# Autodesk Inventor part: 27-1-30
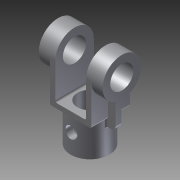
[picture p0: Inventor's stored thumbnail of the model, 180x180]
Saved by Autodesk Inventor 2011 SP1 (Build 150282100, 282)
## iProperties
Created: 2014-02
Part Number: 27-1-30
Document SubType Name: Modeling
Designer: Administrator
Density: 1 g/cm^3
Author: Administrator
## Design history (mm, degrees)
sketch "草图1"
  geometry: C1 r 20 at (0, 0); 1 further point
  constraints: 1 centre point, 1 coincident
  dimensions: "d0" = 40 diameter of C1
extrude "拉伸1" new body sketch "草图1" distance "d1" = 34; taper "d2" = 0 deg
node "工作平面1"
sketch "草图2"
  geometry: L1 (-20, 0)-(20, 0) reference; C1 r 6 at (0, 20); 1 further point
  constraints: 1 centre point
  dimensions: "d4" = 12 diameter of C1; "d5" = 20 distance of point (0, 0) C1.centre
extrude "拉伸2" cut sketch "草图2" stored distance "d6" = 34; taper "d7" = 0 deg
node "工作平面2"
sketch "草图3"
  geometry: L1 (-20, 34)-(20, 34) reference; C1 r 20 at (0, 76); 1 further point
  constraints: 1 centre point
  dimensions: "d9" = 40 diameter of C1; "d10" = 42 distance from line of L1 C1.centre
extrude "拉伸3" join sketch "草图3" distance "d11" = 17; taper "d12" = 0 deg
hole "Hole1" diameter "d15" = 24; stored, may be unused: countersink angle "d19" = 90 deg, drill point angle "d21" = 118 deg; dims "d13" = 10, "d14" = 10, "d16" = 6, "d17" = 4, "d18" = 2, "d20" = 8
sketch "草图4"
  geometry: L1 (-20, 34)-(20, 34) reference; L2 (20, 76)-(20, 34); L3 (-20, 76)-(-20, 34); A1 r 20 centre (0, 76) between (20, 76) and (-20, 76) reference; 1 further point
  constraints: 4 end point, 2 point on circle, 2 tangent, 1 parallel, 1 perpendicular
extrude "拉伸4" join sketch "草图4" distance "d22" = 5.5; taper "d23" = 0 deg
sketch "草图5"
  geometry: L1 (20, 34)-(20, 76) reference; L2 (-20, 76)-(-20, 34) reference; L3 (-20, 34)-(20, 34) reference; L4 (20, 39)-(-20, 39); L5 (-20, 39)-(-20, 34); L6 (-20, 34)-(20, 34); L7 (20, 34)-(20, 39); 3 further points
  constraints: 8 end point, 2 parallel, 1 horizontal, 1 perpendicular, 1 point on line
  dimensions: "d24" = 5 distance of L4.end L2.end
mirror "镜像1"
extrude "拉伸5" join sketch "草图5" stored distance "d25" = 33; taper "d26" = 0 deg
hole "Hole2" diameter "d29" = 26; stored, may be unused: countersink angle "d33" = 90 deg, drill point angle "d35" = 118 deg; dims "d27" = 10, "d28" = 10, "d30" = 6, "d31" = 4, "d32" = 2, "d34" = 8
sketch "草图6"
  geometry: L1 (-21.5, 56)-(-33, 56) reference; L2 (-21.5, 76)-(-21.5, 34) reference; L3 (0, 34)-(-21.5, 34) reference; L4 (-20, 0)-(-20, 34) reference; L5 (-33, 56)-(-33, 96) reference; L6 (-29.5, 56)-(-29.5, 27); L7 (-29.5, 27)-(-20, 27); 1 further point
  constraints: 4 end point, 2 point on line, 1 parallel, 1 perpendicular
  dimensions: "d36" = 3.5 distance of L6.start L1.end; "d37" = 29 distance of L6.start L6.end
feature "加强筋1" sketch "草图6" dims "d38" = 1, "d39" = 6, "d40" = 0
mirror "镜像2"
fillet "圆角1" dims "d41" = 5
fillet "圆角2" dims "d42" = 2
fillet "圆角3" dims "d43" = 2
node "实体1"
other parameters: "d8" = 16
